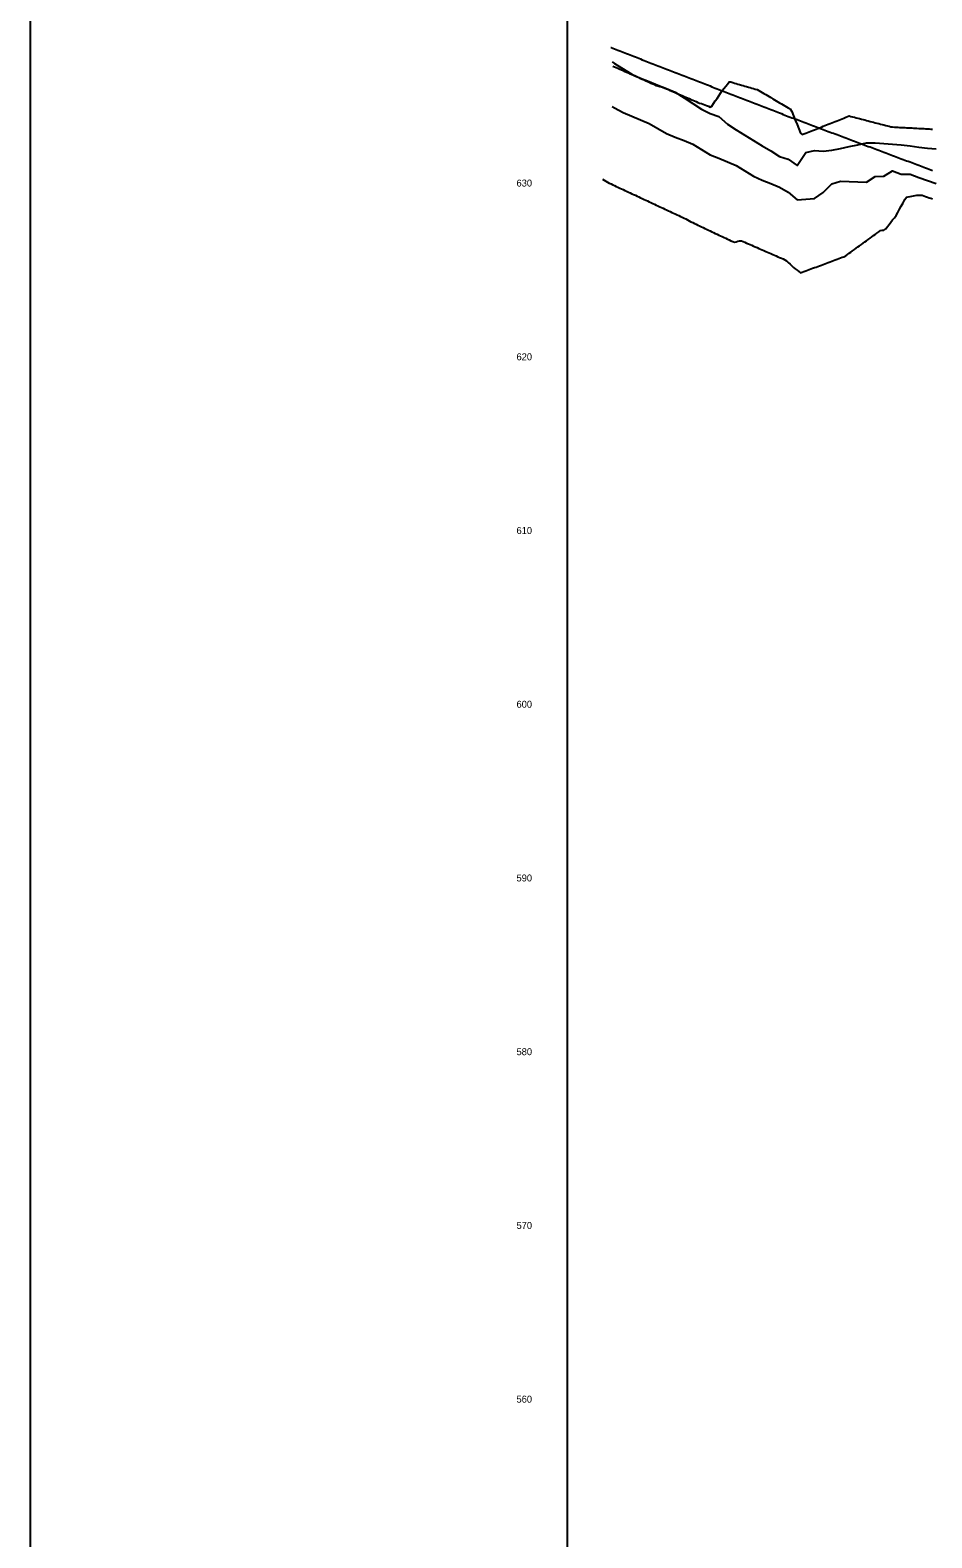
# Model space of a CAD drawing. Extents: x 1733571 to 1737171, y 1214895 to 1219895.
# Drawn here: x 1733571 to 1734090, y 1217920 to 1218788 of the extents above; entities that cross this region are included whole.
import ezdxf

# ---------------------------------------------------------------- set-up
doc = ezdxf.new("R2010")
doc.units = 0
for name, color, linetype in [('Default', 7, 'Continuous'), ('RD_DDB_ElevTX', 7, 'Continuous'), ('RD_DDB_Profile_EX', 7, 'Continuous'), ('RD_Sketch1', 7, 'Continuous'), ('RD_Sketch2', 7, 'Continuous'), ('RD_Sketch3', 7, 'Continuous'), ('RD_Sketch4', 7, 'Continuous'), ('RD_Sketch8', 7, 'Continuous')]:
    doc.layers.add(name, color=color, linetype=linetype)

msp = doc.modelspace()

# ---------------------------------------------------------------- linework, layer by layer
at = {"layer": 'Default'}
msp.add_line((1733880.0087, 1217395.4951), (1733880.0087, 1219895.4951), dxfattribs=at)
at = {"layer": 'RD_DDB_Profile_EX'}
for points in [[(1733904.8087, 1218777.56696), (1733904.9887, 1218777.49829), (1733905.9887, 1218777.11022), (1733906.9887, 1218776.72215), (1733907.9887, 1218776.33407), (1733908.9887, 1218775.946), (1733909.9887, 1218775.55793), (1733910.9887, 1218775.16986), (1733911.9887, 1218774.78178), (1733912.9887, 1218774.39371), (1733913.9887, 1218774.00564), (1733914.9887, 1218773.61757), (1733915.9887, 1218773.22949), (1733916.9887, 1218772.84142), (1733917.9887, 1218772.45335), (1733918.9887, 1218772.06527), (1733919.9887, 1218771.6772), (1733920.9887, 1218771.28913), (1733921.9887, 1218770.90106), (1733922.9887, 1218770.51298), (1733923.9887, 1218770.12491), (1733924.9887, 1218769.73684), (1733925.9887, 1218769.34877), (1733926.9887, 1218768.96069), (1733927.9887, 1218768.57262), (1733928.9887, 1218768.18233), (1733929.9887, 1218767.78898), (1733930.9887, 1218767.40087), (1733931.9887, 1218767.01276), (1733932.9887, 1218766.62466), (1733933.9887, 1218766.23655), (1733934.9887, 1218765.84845), (1733935.9887, 1218765.46034), (1733936.9887, 1218765.07223), (1733937.9887, 1218764.68413), (1733938.9887, 1218764.29602), (1733939.9887, 1218763.90792), (1733940.9887, 1218763.51981), (1733941.9887, 1218763.1317), (1733942.9887, 1218762.7436), (1733943.9887, 1218762.35549), (1733944.9887, 1218761.96739), (1733945.9887, 1218761.57928), (1733946.9887, 1218761.19118), (1733947.9887, 1218760.80307), (1733948.9887, 1218760.41496), (1733949.9887, 1218760.02686), (1733950.9887, 1218759.63875), (1733951.9887, 1218759.25065), (1733952.9887, 1218758.86254), (1733953.9887, 1218758.47132), (1733954.9887, 1218758.07807), (1733955.9887, 1218757.68993), (1733956.9887, 1218757.30179), (1733957.9887, 1218756.91365), (1733958.9887, 1218756.52551), (1733959.9887, 1218756.13737), (1733960.9887, 1218755.74923), (1733961.9887, 1218755.36109), (1733962.9887, 1218754.97296), (1733963.9887, 1218754.58482), (1733964.9887, 1218754.19668), (1733965.9887, 1218753.80854), (1733966.9887, 1218753.4204), (1733967.9887, 1218753.03226), (1733968.9887, 1218752.64412), (1733969.9887, 1218752.25598), (1733970.9887, 1218751.86784), (1733971.9887, 1218751.47971), (1733972.9887, 1218751.09157), (1733973.9887, 1218750.70343), (1733974.9887, 1218750.31529), (1733975.9887, 1218749.92715), (1733976.9887, 1218749.53901), (1733977.9887, 1218749.15087), (1733978.9887, 1218748.75874), (1733979.9887, 1218748.36558), (1733980.9887, 1218747.97741), (1733981.9887, 1218747.58924), (1733982.9887, 1218747.20107), (1733983.9887, 1218746.8129), (1733984.9887, 1218746.42473), (1733985.9887, 1218746.03655), (1733986.9887, 1218745.64838), (1733987.9887, 1218745.26021), (1733988.9887, 1218744.87204), (1733989.9887, 1218744.48387), (1733990.9887, 1218744.0957), (1733991.9887, 1218743.70752), (1733992.9887, 1218743.31935), (1733993.9887, 1218742.93118), (1733994.9887, 1218742.54301), (1733995.9887, 1218742.15484), (1733996.9887, 1218741.76667), (1733997.9887, 1218741.3785), (1733998.9887, 1218740.99032), (1733999.9887, 1218740.60215), (1734000.9887, 1218740.21398), (1734001.9887, 1218739.82581), (1734002.9887, 1218739.43764), (1734003.9887, 1218739.0446)], [(1734003.9887, 1218739.0446), (1734004.9887, 1218738.65155), (1734005.9887, 1218738.26334), (1734006.9887, 1218737.87821), (1734007.9887, 1218737.50358), (1734008.9887, 1218737.12895), (1734009.9887, 1218736.75432), (1734010.9887, 1218736.37969), (1734011.9887, 1218736.00506), (1734012.9887, 1218735.63043), (1734013.9887, 1218735.2558), (1734014.9887, 1218734.88117), (1734015.9887, 1218734.50654), (1734016.9887, 1218734.13191), (1734017.9887, 1218733.75728), (1734018.9887, 1218733.38265), (1734019.9887, 1218733.00802), (1734020.9887, 1218732.63339), (1734021.9887, 1218732.25876), (1734022.9887, 1218731.88413), (1734023.9887, 1218731.5095), (1734024.9887, 1218731.13487), (1734025.9887, 1218730.76024), (1734026.9887, 1218730.38561), (1734027.9887, 1218730.01098), (1734028.9887, 1218729.63635), (1734029.9887, 1218729.26172), (1734030.9887, 1218728.8777), (1734031.9887, 1218728.4914), (1734032.9887, 1218728.11697), (1734033.9887, 1218727.74254), (1734034.9887, 1218727.36811), (1734035.9887, 1218726.99367), (1734036.9887, 1218726.61924), (1734037.9887, 1218726.24481), (1734038.9887, 1218725.87038), (1734039.9887, 1218725.49594), (1734040.9887, 1218725.12151), (1734041.9887, 1218724.74708), (1734042.9887, 1218724.37265), (1734043.9887, 1218723.99821), (1734044.9887, 1218723.62378), (1734045.9887, 1218723.24935), (1734046.9887, 1218722.87492), (1734047.9887, 1218722.50049), (1734048.9887, 1218722.12605), (1734049.9887, 1218721.75162), (1734050.9887, 1218721.37719), (1734051.9887, 1218721.00276), (1734052.9887, 1218720.62832), (1734053.9887, 1218720.25389), (1734054.9887, 1218719.87946), (1734055.9887, 1218719.49991), (1734056.9887, 1218719.11407), (1734057.9887, 1218718.73984), (1734058.9887, 1218718.36561), (1734059.9887, 1218717.99138), (1734060.9887, 1218717.61715), (1734061.9887, 1218717.24292), (1734062.9887, 1218716.86869), (1734063.9887, 1218716.49446), (1734064.9887, 1218716.12023), (1734065.9887, 1218715.746), (1734066.9887, 1218715.37177), (1734067.9887, 1218714.99754), (1734068.9887, 1218714.62332), (1734069.9887, 1218714.24909), (1734070.9887, 1218713.87486), (1734071.9887, 1218713.50063), (1734072.9887, 1218713.1264), (1734073.9887, 1218712.75217), (1734074.9887, 1218712.37794), (1734075.9887, 1218712.00371), (1734076.9887, 1218711.62948), (1734077.9887, 1218711.25525), (1734078.9887, 1218710.88102), (1734079.9887, 1218710.50679), (1734080.9887, 1218710.13195), (1734081.9887, 1218709.74658), (1734082.9887, 1218709.37256), (1734083.9887, 1218708.99854), (1734084.9887, 1218708.62451), (1734085.9887, 1218708.25049), (1734086.9887, 1218707.87647), (1734087.9887, 1218707.50245), (1734088.9887, 1218707.12843), (1734089.9887, 1218706.75441)]]:
    msp.add_lwpolyline(points, dxfattribs=at)
at = {"layer": 'RD_Sketch1'}
for points in [[(1733906.0187, 1218766.75297), (1733906.9887, 1218766.44513), (1733907.9887, 1218766.03889), (1733908.9887, 1218765.58853), (1733909.9887, 1218765.13816), (1733910.9887, 1218764.68779), (1733911.9887, 1218764.23742), (1733912.9887, 1218763.78705), (1733913.9887, 1218763.33669), (1733914.9887, 1218762.88632), (1733915.9887, 1218762.43595), (1733916.9887, 1218761.98558), (1733917.9887, 1218761.53521), (1733918.9887, 1218761.08484), (1733919.9887, 1218760.63448), (1733920.9887, 1218760.18411), (1733921.9887, 1218759.73374), (1733922.9887, 1218759.28337), (1733923.9887, 1218758.833), (1733924.9887, 1218758.38264), (1733925.9887, 1218757.93227), (1733926.9887, 1218757.4819), (1733927.9887, 1218757.03153), (1733928.9887, 1218756.58116), (1733929.9887, 1218756.1308), (1733930.9887, 1218755.68612), (1733931.9887, 1218755.38823), (1733932.9887, 1218755.09033), (1733933.9887, 1218754.79244), (1733934.9887, 1218754.49454), (1733935.9887, 1218754.14227), (1733936.9887, 1218753.70981), (1733937.9887, 1218753.27734), (1733938.9887, 1218752.84487), (1733939.9887, 1218752.4124), (1733940.9887, 1218751.97993), (1733941.9887, 1218751.54746), (1733942.9887, 1218751.115), (1733943.9887, 1218750.68253), (1733944.9887, 1218750.25006), (1733945.9887, 1218749.81759), (1733946.9887, 1218749.38512), (1733947.9887, 1218748.95265), (1733948.9887, 1218748.52019), (1733949.9887, 1218748.08772), (1733950.9887, 1218747.65525), (1733951.9887, 1218747.22278), (1733952.9887, 1218746.79031), (1733953.9887, 1218746.35784), (1733954.9887, 1218745.92538), (1733955.9887, 1218745.5083), (1733956.9887, 1218745.22981), (1733957.9887, 1218744.94499), (1733958.9887, 1218744.51765), (1733959.9887, 1218744.0903), (1733960.9887, 1218743.66296), (1733961.9887, 1218743.23561), (1733962.9887, 1218743.76338), (1733963.9887, 1218745.25752), (1733964.9887, 1218746.75166), (1733965.9887, 1218748.2458), (1733966.9887, 1218749.73995), (1733967.9887, 1218751.23409), (1733968.9887, 1218752.72823), (1733969.9887, 1218754.08336), (1733970.9887, 1218755.27722), (1733971.9887, 1218756.47107), (1733972.9887, 1218757.66493), (1733973.9887, 1218757.66061), (1733974.9887, 1218757.36686), (1733975.9887, 1218757.07311), (1733976.9887, 1218756.77935), (1733977.9887, 1218756.4856), (1733978.9887, 1218756.19184), (1733979.9887, 1218755.89809), (1733980.9887, 1218755.60434), (1733981.9887, 1218755.31058), (1733982.9887, 1218755.01683), (1733983.9887, 1218754.72308), (1733984.9887, 1218754.42932), (1733985.9887, 1218754.13557), (1733986.9887, 1218753.84181), (1733987.9887, 1218753.54806), (1733988.9887, 1218753.25431), (1733989.9887, 1218752.79641), (1733990.9887, 1218752.20477), (1733991.9887, 1218751.61313), (1733992.9887, 1218751.02148), (1733993.9887, 1218750.42984), (1733994.9887, 1218749.8382), (1733995.9887, 1218749.24656), (1733996.9887, 1218748.65492), (1733997.9887, 1218748.06327), (1733998.9887, 1218747.47163), (1733999.9887, 1218746.87999), (1734000.9887, 1218746.28835), (1734001.9887, 1218745.69671), (1734002.9887, 1218745.10507), (1734003.9887, 1218744.51342), (1734004.9887, 1218743.92178), (1734005.9887, 1218743.33014)], [(1734005.9887, 1218743.33014), (1734006.9887, 1218742.7385), (1734007.9887, 1218742.14686), (1734008.9887, 1218740.67352), (1734009.9887, 1218738.18492), (1734010.9887, 1218735.69631), (1734011.9887, 1218733.2077), (1734012.9887, 1218730.71909), (1734013.9887, 1218728.23048), (1734014.9887, 1218727.35314), (1734015.9887, 1218727.75233), (1734016.9887, 1218728.15152), (1734017.9887, 1218728.55071), (1734018.9887, 1218728.9499), (1734019.9887, 1218729.3491), (1734020.9887, 1218729.74829), (1734021.9887, 1218730.14748), (1734022.9887, 1218730.54667), (1734023.9887, 1218730.94586), (1734024.9887, 1218731.34505), (1734025.9887, 1218731.74424), (1734026.9887, 1218732.14343), (1734027.9887, 1218732.54262), (1734028.9887, 1218732.94181), (1734029.9887, 1218733.34101), (1734030.9887, 1218733.7402), (1734031.9887, 1218734.13939), (1734032.9887, 1218734.53858), (1734033.9887, 1218734.93777), (1734034.9887, 1218735.33696), (1734035.9887, 1218735.73615), (1734036.9887, 1218736.13534), (1734037.9887, 1218736.53453), (1734038.9887, 1218736.93372), (1734039.9887, 1218737.33292), (1734040.9887, 1218737.73211), (1734041.9887, 1218738.1274), (1734042.9887, 1218737.86826), (1734043.9887, 1218737.60911), (1734044.9887, 1218737.34996), (1734045.9887, 1218737.09081), (1734046.9887, 1218736.83166), (1734047.9887, 1218736.57252), (1734048.9887, 1218736.31337), (1734049.9887, 1218736.05422), (1734050.9887, 1218735.79507), (1734051.9887, 1218735.53593), (1734052.9887, 1218735.27678), (1734053.9887, 1218735.01763), (1734054.9887, 1218734.75848), (1734055.9887, 1218734.49933), (1734056.9887, 1218734.24019), (1734057.9887, 1218733.98104), (1734058.9887, 1218733.72189), (1734059.9887, 1218733.46274), (1734060.9887, 1218733.2036), (1734061.9887, 1218732.94445), (1734062.9887, 1218732.6853), (1734063.9887, 1218732.42615), (1734064.9887, 1218732.16701), (1734065.9887, 1218731.90786), (1734066.9887, 1218731.77653), (1734067.9887, 1218731.72333), (1734068.9887, 1218731.67013), (1734069.9887, 1218731.61693), (1734070.9887, 1218731.56373), (1734071.9887, 1218731.51053), (1734072.9887, 1218731.45733), (1734073.9887, 1218731.40413), (1734074.9887, 1218731.35093), (1734075.9887, 1218731.29773), (1734076.9887, 1218731.24453), (1734077.9887, 1218731.19133), (1734078.9887, 1218731.13813), (1734079.9887, 1218731.08493), (1734080.9887, 1218731.03173), (1734081.9887, 1218730.97853), (1734082.9887, 1218730.92533), (1734083.9887, 1218730.87213), (1734084.9887, 1218730.81893), (1734085.9887, 1218730.76573), (1734086.9887, 1218730.71253), (1734087.9887, 1218730.65933), (1734088.9887, 1218730.60613), (1734089.9887, 1218730.55293)]]:
    msp.add_lwpolyline(points, dxfattribs=at)
at = {"layer": 'RD_Sketch2'}
for points in [[(1733900.1087, 1218701.66046), (1733900.9887, 1218701.15384), (1733901.9887, 1218700.57508), (1733902.9887, 1218699.99633), (1733903.9887, 1218699.44507), (1733904.9887, 1218698.97803), (1733905.9887, 1218698.51099), (1733906.9887, 1218698.04394), (1733907.9887, 1218697.5769), (1733908.9887, 1218697.10986), (1733909.9887, 1218696.64282), (1733910.9887, 1218696.17578), (1733911.9887, 1218695.70874), (1733912.9887, 1218695.2417), (1733913.9887, 1218694.77466), (1733914.9887, 1218694.30762), (1733915.9887, 1218693.84058), (1733916.9887, 1218693.37354), (1733917.9887, 1218692.9065), (1733918.9887, 1218692.43945), (1733919.9887, 1218691.97241), (1733920.9887, 1218691.50537), (1733921.9887, 1218691.03833), (1733922.9887, 1218690.57129), (1733923.9887, 1218690.10425), (1733924.9887, 1218689.63721), (1733925.9887, 1218689.17017), (1733926.9887, 1218688.70313), (1733927.9887, 1218688.23609), (1733928.9887, 1218687.76905), (1733929.9887, 1218687.30201), (1733930.9887, 1218686.83497), (1733931.9887, 1218686.36792), (1733932.9887, 1218685.90088), (1733933.9887, 1218685.43384), (1733934.9887, 1218684.9668), (1733935.9887, 1218684.49976), (1733936.9887, 1218684.03272), (1733937.9887, 1218683.56568), (1733938.9887, 1218683.09864), (1733939.9887, 1218682.6316), (1733940.9887, 1218682.16456), (1733941.9887, 1218681.69752), (1733942.9887, 1218681.23048), (1733943.9887, 1218680.76343), (1733944.9887, 1218680.29639), (1733945.9887, 1218679.82935), (1733946.9887, 1218679.36231), (1733947.9887, 1218678.87156), (1733948.9887, 1218678.3263), (1733949.9887, 1218677.78104), (1733950.9887, 1218677.23578), (1733951.9887, 1218676.69947), (1733952.9887, 1218676.22564), (1733953.9887, 1218675.75181), (1733954.9887, 1218675.27797), (1733955.9887, 1218674.80414), (1733956.9887, 1218674.33031), (1733957.9887, 1218673.85648), (1733958.9887, 1218673.38265), (1733959.9887, 1218672.90882), (1733960.9887, 1218672.43498), (1733961.9887, 1218671.96115), (1733962.9887, 1218671.48732), (1733963.9887, 1218671.01349), (1733964.9887, 1218670.53966), (1733965.9887, 1218670.06582), (1733966.9887, 1218669.59199), (1733967.9887, 1218669.11816), (1733968.9887, 1218668.64433), (1733969.9887, 1218668.1705), (1733970.9887, 1218667.69667), (1733971.9887, 1218667.22283), (1733972.9887, 1218666.749), (1733973.9887, 1218666.27517), (1733974.9887, 1218665.80134), (1733975.9887, 1218665.4104), (1733976.9887, 1218665.68669), (1733977.9887, 1218665.96298), (1733978.9887, 1218666.23927), (1733979.9887, 1218666.28148), (1733980.9887, 1218665.84502), (1733981.9887, 1218665.40856), (1733982.9887, 1218664.97209), (1733983.9887, 1218664.53563), (1733984.9887, 1218664.09917), (1733985.9887, 1218663.66271), (1733986.9887, 1218663.22625), (1733987.9887, 1218662.78978), (1733988.9887, 1218662.35332), (1733989.9887, 1218661.91686), (1733990.9887, 1218661.4804), (1733991.9887, 1218661.04394), (1733992.9887, 1218660.60747), (1733993.9887, 1218660.17101), (1733994.9887, 1218659.73455), (1733995.9887, 1218659.29809), (1733996.9887, 1218658.86163), (1733997.9887, 1218658.42516), (1733998.9887, 1218657.9887), (1733999.9887, 1218657.55224)], [(1733999.9887, 1218657.55224), (1734000.9887, 1218657.11578), (1734001.9887, 1218656.67931), (1734002.9887, 1218656.24285), (1734003.9887, 1218655.80639), (1734004.9887, 1218655.36993), (1734005.9887, 1218654.79193), (1734006.9887, 1218653.82793), (1734007.9887, 1218652.86394), (1734008.9887, 1218651.89994), (1734009.9887, 1218650.93594), (1734010.9887, 1218650.13194), (1734011.9887, 1218649.32911), (1734012.9887, 1218648.60499), (1734013.9887, 1218647.88401), (1734014.9887, 1218648.18617), (1734015.9887, 1218648.55847), (1734016.9887, 1218648.93076), (1734017.9887, 1218649.30306), (1734018.9887, 1218649.67536), (1734019.9887, 1218650.04766), (1734020.9887, 1218650.41996), (1734021.9887, 1218650.79225), (1734022.9887, 1218651.16455), (1734023.9887, 1218651.53685), (1734024.9887, 1218651.90915), (1734025.9887, 1218652.28144), (1734026.9887, 1218652.65374), (1734027.9887, 1218653.02604), (1734028.9887, 1218653.39834), (1734029.9887, 1218653.77063), (1734030.9887, 1218654.14293), (1734031.9887, 1218654.51523), (1734032.9887, 1218654.88753), (1734033.9887, 1218655.25982), (1734034.9887, 1218655.63212), (1734035.9887, 1218656.00442), (1734036.9887, 1218656.37672), (1734037.9887, 1218656.74901), (1734038.9887, 1218657.12131), (1734039.9887, 1218657.5924), (1734040.9887, 1218658.32041), (1734041.9887, 1218659.04842), (1734042.9887, 1218659.77643), (1734043.9887, 1218660.50443), (1734044.9887, 1218661.23244), (1734045.9887, 1218661.96045), (1734046.9887, 1218662.68846), (1734047.9887, 1218663.41647), (1734048.9887, 1218664.14448), (1734049.9887, 1218664.87249), (1734050.9887, 1218665.6005), (1734051.9887, 1218666.32851), (1734052.9887, 1218667.05652), (1734053.9887, 1218667.78453), (1734054.9887, 1218668.51254), (1734055.9887, 1218669.24055), (1734056.9887, 1218669.96855), (1734057.9887, 1218670.69656), (1734058.9887, 1218671.42457), (1734059.9887, 1218672.15258), (1734060.9887, 1218672.32202), (1734061.9887, 1218672.33903), (1734062.9887, 1218673.18464), (1734063.9887, 1218674.45026), (1734064.9887, 1218675.71588), (1734065.9887, 1218676.9815), (1734066.9887, 1218678.24712), (1734067.9887, 1218679.51275), (1734068.9887, 1218680.77837), (1734069.9887, 1218682.47025), (1734070.9887, 1218684.36973), (1734071.9887, 1218686.26921), (1734072.9887, 1218688.16869), (1734073.9887, 1218690.06817), (1734074.9887, 1218691.40927), (1734075.9887, 1218691.58938), (1734076.9887, 1218691.7695), (1734077.9887, 1218691.94962), (1734078.9887, 1218692.12974), (1734079.9887, 1218692.30986), (1734080.9887, 1218692.48998), (1734081.9887, 1218692.61352), (1734082.9887, 1218692.52494), (1734083.9887, 1218692.43636), (1734084.9887, 1218692.16711), (1734085.9887, 1218691.80345), (1734086.9887, 1218691.43979), (1734087.9887, 1218691.07612), (1734088.9887, 1218690.71246), (1734089.9887, 1218690.3488)]]:
    msp.add_lwpolyline(points, dxfattribs=at)
at = {"layer": 'RD_Sketch3'}
msp.add_lwpolyline([(1733905.6087, 1218769.17438), (1733906.9887, 1218768.32257), (1733911.9887, 1218765.23692), (1733916.9887, 1218762.15127), (1733921.9887, 1218759.81196), (1733926.9887, 1218757.86362), (1733931.9887, 1218755.90829), (1733936.9887, 1218753.93468), (1733941.9887, 1218751.7853), (1733946.9887, 1218748.55876), (1733951.9887, 1218745.33221), (1733956.9887, 1218742.10567), (1733961.9887, 1218739.57582), (1733966.9887, 1218737.7648), (1733971.9887, 1218733.44291), (1733976.9887, 1218730.08848), (1733981.9887, 1218727.02036), (1733986.9887, 1218723.95223), (1733991.9887, 1218720.88411), (1733996.9887, 1218718.07021), (1734001.9887, 1218714.86186), (1734006.9887, 1218713.27345), (1734011.9887, 1218709.65589), (1734016.9887, 1218717.12266), (1734021.9887, 1218718.18199), (1734026.9887, 1218717.85687), (1734031.9887, 1218718.37281), (1734036.9887, 1218719.43201), (1734041.9887, 1218720.49121), (1734046.9887, 1218721.55041), (1734051.9887, 1218722.60962), (1734056.9887, 1218722.59599), (1734061.9887, 1218722.2477), (1734066.9887, 1218721.89941), (1734071.9887, 1218721.55112), (1734076.9887, 1218720.92535), (1734081.9887, 1218720.12378), (1734086.9887, 1218719.64255), (1734091.9887, 1218719.16132)], dxfattribs=at)
at = {"layer": 'RD_Sketch4'}
msp.add_lwpolyline([(1733905.6087, 1218743.5956), (1733906.9887, 1218742.79692), (1733911.9887, 1218740.07349), (1733916.9887, 1218738.00579), (1733921.9887, 1218735.93808), (1733926.9887, 1218733.84729), (1733931.9887, 1218730.89758), (1733936.9887, 1218728.05194), (1733941.9887, 1218725.99105), (1733946.9887, 1218723.93017), (1733951.9887, 1218721.82724), (1733956.9887, 1218718.81246), (1733961.9887, 1218715.8088), (1733966.9887, 1218713.75593), (1733971.9887, 1218711.70307), (1733976.9887, 1218709.58348), (1733981.9887, 1218706.49208), (1733986.9887, 1218703.40068), (1733991.9887, 1218701.23672), (1733996.9887, 1218699.19342), (1734001.9887, 1218697.05058), (1734006.9887, 1218694.17748), (1734011.9887, 1218689.82633), (1734016.9887, 1218690.20166), (1734021.9887, 1218690.57698), (1734026.9887, 1218694.06419), (1734031.9887, 1218699.13626), (1734036.9887, 1218700.52479), (1734041.9887, 1218700.372), (1734046.9887, 1218700.21921), (1734051.9887, 1218700.06642), (1734056.9887, 1218703.22399), (1734061.9887, 1218703.45948), (1734066.9887, 1218706.50846), (1734071.9887, 1218704.63446), (1734076.9887, 1218704.64865), (1734081.9887, 1218702.74105), (1734086.9887, 1218700.91013), (1734091.9887, 1218699.25216)], dxfattribs=at)
at = {"layer": 'RD_Sketch8'}
msp.add_lwpolyline([(1733570.87731, 1217025.61718), (1737170.87731, 1217025.61718), (1737170.87731, 1219225.61718), (1733570.87731, 1219225.61718)], close=True, dxfattribs=at)

# ---------------------------------------------------------------- texts
at = {"layer": 'RD_DDB_ElevTX'}
for s, p in [('630', (1733850.64176, 1218697.4951)), ('630', (1733850.64176, 1218697.4951)), ('630', (1733850.64176, 1218697.4951)), ('620', (1733850.64176, 1218597.4951)), ('620', (1733850.64176, 1218597.4951)), ('620', (1733850.64176, 1218597.4951)), ('610', (1733850.64176, 1218497.4951)), ('610', (1733850.64176, 1218497.4951)), ('610', (1733850.64176, 1218497.4951)), ('600', (1733850.64176, 1218397.4951)), ('600', (1733850.64176, 1218397.4951)), ('600', (1733850.64176, 1218397.4951)), ('590', (1733850.64176, 1218297.4951)), ('590', (1733850.64176, 1218297.4951)), ('590', (1733850.64176, 1218297.4951)), ('580', (1733850.64176, 1218197.4951)), ('580', (1733850.64176, 1218197.4951)), ('580', (1733850.64176, 1218197.4951)), ('570', (1733850.64176, 1218097.4951)), ('570', (1733850.64176, 1218097.4951)), ('570', (1733850.64176, 1218097.4951)), ('560', (1733850.64176, 1217997.4951)), ('560', (1733850.64176, 1217997.4951)), ('560', (1733850.64176, 1217997.4951))]:
    msp.add_text(s, height=4, dxfattribs=at).set_placement(p)

doc.saveas('drawing.dxf')
